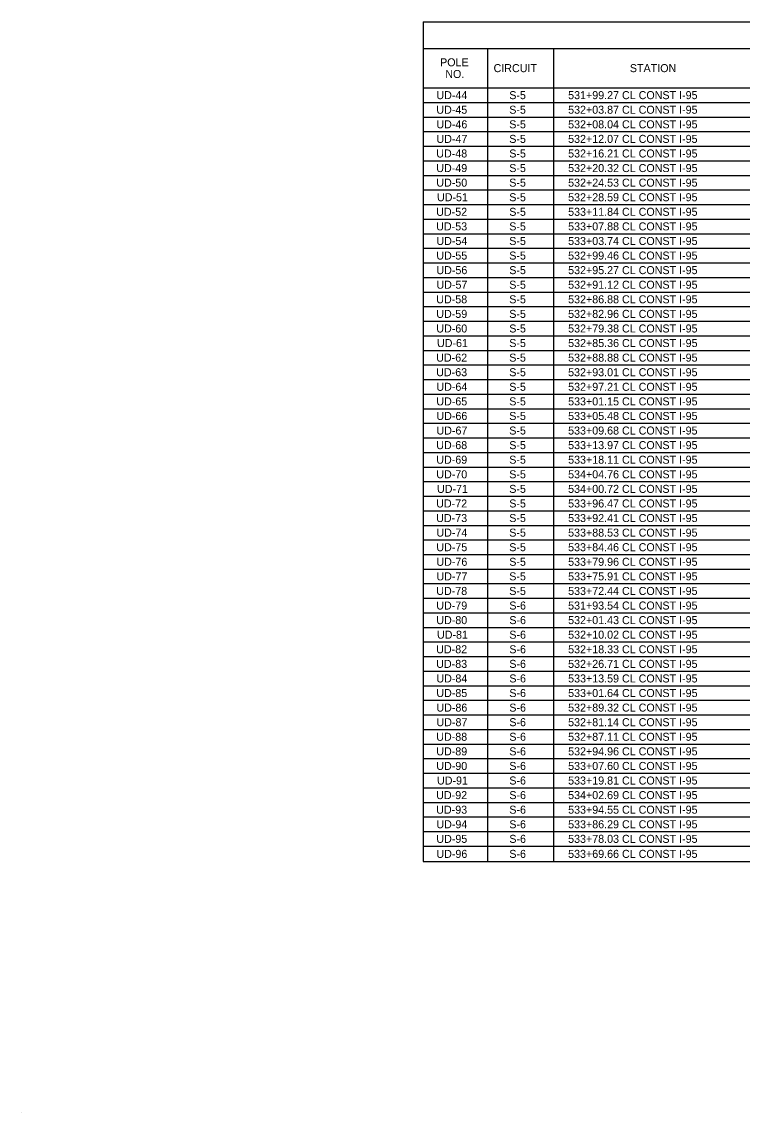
# Model space of a CAD drawing. Extents: x -816.7 to -800.9, y -2209.6 to -2187.8.
# Drawn here: x -816.67 to -810.37, y -2209.64 to -2200.11 of the extents above; entities that cross this region are included whole.
import ezdxf

# ---------------------------------------------------------------- set-up
doc = ezdxf.new("R2010")
doc.units = 0
for name, color, linetype in [('PlotBorder_dp', 7, 'Continuous'), ('SheetBorder_dp', 7, 'Continuous'), ('SheetLines_dp', 7, 'Continuous'), ('TextMinor', 7, 'Continuous'), ('TextShtNo', 7, 'Continuous')]:
    doc.layers.add(name, color=color, linetype=linetype)

msp = doc.modelspace()

# ---------------------------------------------------------------- linework, layer by layer
at = {"layer": 'PlotBorder_dp'}
for p, q in [((-812.5961, -2200.3435), (-812.5961, -2207.4535)), ((-812.5961, -2200.3435), (-812.5961, -2207.4535)), ((-812.0186, -2200.3435), (-812.0186, -2207.4535)), ((-812.0186, -2200.3435), (-812.0186, -2207.4535)), ((-813.1586, -2200.6885), (-802.8536, -2200.6885))]:
    msp.add_line(p, q, dxfattribs=at)
at = {"layer": 'SheetLines_dp'}
for p, q in [((-813.1586, -2200.111), (-802.8536, -2200.111)), ((-813.1586, -2200.111), (-813.1586, -2207.4535)), ((-813.1586, -2200.3435), (-802.8536, -2200.3435)), ((-813.1586, -2200.3435), (-802.8536, -2200.3435)), ((-813.1586, -2207.4535), (-802.8536, -2207.4535))]:
    msp.add_line(p, q, dxfattribs=at)
at = {"layer": 'TextMinor'}
for p, q in [((-813.1586, -2200.6885), (-802.8536, -2200.6885)), ((-813.1586, -2200.816), (-802.8536, -2200.816)), ((-813.1586, -2200.816), (-802.8536, -2200.816)), ((-813.1586, -2200.9435), (-802.8536, -2200.9435)), ((-813.1586, -2200.9435), (-802.8536, -2200.9435)), ((-813.1586, -2201.071), (-802.8536, -2201.071)), ((-813.1586, -2201.071), (-802.8536, -2201.071)), ((-813.1586, -2201.1985), (-802.8536, -2201.1985)), ((-813.1586, -2201.1985), (-802.8536, -2201.1985)), ((-813.1586, -2201.326), (-802.8536, -2201.326)), ((-813.1586, -2201.326), (-802.8536, -2201.326)), ((-813.1586, -2201.4535), (-812.0186, -2201.4535)), ((-813.1586, -2201.4535), (-802.8536, -2201.4535)), ((-813.1586, -2201.581), (-802.8536, -2201.581)), ((-813.1586, -2201.581), (-802.8536, -2201.581)), ((-813.1586, -2201.7085), (-802.8536, -2201.7085)), ((-813.1586, -2201.7085), (-802.8536, -2201.7085)), ((-813.1586, -2201.836), (-802.8536, -2201.836)), ((-813.1586, -2201.836), (-802.8536, -2201.836)), ((-813.1586, -2201.9635), (-802.8536, -2201.9635)), ((-813.1586, -2201.9635), (-802.8536, -2201.9635)), ((-813.1586, -2202.091), (-802.8536, -2202.091)), ((-813.1586, -2202.091), (-802.8536, -2202.091)), ((-813.1586, -2202.2185), (-802.8536, -2202.2185)), ((-813.1586, -2202.2185), (-802.8536, -2202.2185)), ((-813.1586, -2202.346), (-802.8536, -2202.346)), ((-813.1586, -2202.346), (-802.8536, -2202.346)), ((-813.1586, -2202.4735), (-802.8536, -2202.4735)), ((-813.1586, -2202.4735), (-802.8536, -2202.4735)), ((-813.1586, -2202.601), (-802.8536, -2202.601)), ((-813.1586, -2202.601), (-802.8536, -2202.601)), ((-813.1586, -2202.7285), (-802.8536, -2202.7285)), ((-813.1586, -2202.7285), (-802.8536, -2202.7285)), ((-813.1586, -2202.856), (-802.8536, -2202.856)), ((-813.1586, -2202.856), (-802.8536, -2202.856)), ((-813.1586, -2202.9835), (-802.8536, -2202.9835)), ((-813.1586, -2202.9835), (-802.8536, -2202.9835)), ((-813.1586, -2203.111), (-802.8536, -2203.111)), ((-813.1586, -2203.111), (-802.8536, -2203.111)), ((-813.1586, -2203.2385), (-802.8536, -2203.2385)), ((-813.1586, -2203.2385), (-802.8536, -2203.2385)), ((-813.1586, -2203.366), (-802.8536, -2203.366)), ((-813.1586, -2203.366), (-802.8536, -2203.366)), ((-813.1586, -2203.4935), (-802.8536, -2203.4935)), ((-813.1586, -2203.4935), (-802.8536, -2203.4935)), ((-813.1586, -2203.621), (-802.8536, -2203.621)), ((-813.1586, -2203.621), (-802.8536, -2203.621)), ((-813.1586, -2203.7485), (-802.8536, -2203.7485)), ((-813.1586, -2203.7485), (-802.8536, -2203.7485)), ((-813.1586, -2203.876), (-802.8536, -2203.876)), ((-813.1586, -2203.876), (-802.8536, -2203.876)), ((-813.1586, -2204.0035), (-802.8536, -2204.0035)), ((-813.1586, -2204.0035), (-802.8536, -2204.0035)), ((-813.1586, -2204.131), (-802.8536, -2204.131)), ((-813.1586, -2204.131), (-802.8536, -2204.131)), ((-813.1586, -2204.2585), (-802.8536, -2204.2585)), ((-813.1586, -2204.2585), (-802.8536, -2204.2585)), ((-813.1586, -2204.386), (-802.8536, -2204.386)), ((-813.1586, -2204.386), (-802.8536, -2204.386)), ((-813.1586, -2204.5135), (-802.8536, -2204.5135)), ((-813.1586, -2204.5135), (-802.8536, -2204.5135)), ((-813.1586, -2204.641), (-802.8536, -2204.641)), ((-813.1586, -2204.641), (-802.8536, -2204.641)), ((-813.1586, -2204.7685), (-802.8536, -2204.7685)), ((-813.1586, -2204.7685), (-802.8536, -2204.7685)), ((-813.1586, -2204.896), (-802.8536, -2204.896)), ((-813.1586, -2204.896), (-802.8536, -2204.896)), ((-813.1586, -2205.0235), (-802.8536, -2205.0235)), ((-813.1586, -2205.0235), (-802.8536, -2205.0235)), ((-813.1586, -2205.151), (-802.8536, -2205.151)), ((-812.5961, -2205.151), (-812.0186, -2205.151)), ((-813.1586, -2205.2785), (-802.8536, -2205.2785)), ((-813.1586, -2205.2785), (-802.8536, -2205.2785)), ((-813.1586, -2205.406), (-802.8536, -2205.406)), ((-813.1586, -2205.406), (-802.8536, -2205.406)), ((-813.1586, -2205.5335), (-802.8536, -2205.5335)), ((-813.1586, -2205.5335), (-802.8536, -2205.5335)), ((-813.1586, -2205.661), (-802.8536, -2205.661)), ((-813.1586, -2205.661), (-802.8536, -2205.661)), ((-813.1586, -2205.7885), (-802.8536, -2205.7885)), ((-813.1586, -2205.7885), (-802.8536, -2205.7885)), ((-813.1586, -2205.916), (-812.0186, -2205.916)), ((-813.1586, -2205.916), (-802.8536, -2205.916)), ((-813.1586, -2206.0435), (-802.8536, -2206.0435)), ((-813.1586, -2206.0435), (-802.8536, -2206.0435)), ((-813.1586, -2206.171), (-802.8536, -2206.171)), ((-813.1586, -2206.171), (-802.8536, -2206.171)), ((-813.1586, -2206.2985), (-802.8536, -2206.2985)), ((-813.1586, -2206.2985), (-802.8536, -2206.2985)), ((-813.1586, -2206.426), (-802.8536, -2206.426)), ((-813.1586, -2206.426), (-802.8536, -2206.426)), ((-813.1586, -2206.5535), (-802.8536, -2206.5535)), ((-813.1586, -2206.5535), (-802.8536, -2206.5535)), ((-813.1586, -2206.681), (-802.8536, -2206.681)), ((-813.1586, -2206.681), (-802.8536, -2206.681)), ((-813.1586, -2206.8085), (-802.8536, -2206.8085)), ((-813.1586, -2206.8085), (-802.8536, -2206.8085)), ((-813.1586, -2206.936), (-802.8536, -2206.936)), ((-813.1586, -2206.936), (-802.8536, -2206.936)), ((-813.1586, -2207.0635), (-802.8536, -2207.0635)), ((-813.1586, -2207.0635), (-802.8536, -2207.0635)), ((-813.1586, -2207.191), (-802.8536, -2207.191)), ((-813.1586, -2207.191), (-802.8536, -2207.191)), ((-813.1586, -2207.3185), (-802.8536, -2207.3185)), ((-813.1586, -2207.3185), (-802.8536, -2207.3185))]:
    msp.add_line(p, q, dxfattribs=at)
at = {"layer": 'TextShtNo'}
msp.add_line((-816.6686, -2209.6446), (-816.6686, -2209.6446), dxfattribs=at)

# ---------------------------------------------------------------- texts
at = {"layer": 'SheetBorder_dp'}
for s, p in [('POLE', (-813.0106, -2200.5)), ('NO.', (-812.965, -2200.602)), ('CIRCUIT', (-812.5427, -2200.551)), ('STATION', (-811.3507, -2200.551)), ('UD-44', (-813.0429, -2200.7872)), ('S-5', (-812.4056, -2200.7872)), ('531+99.27 CL CONST I-95', (-811.8907, -2200.7872)), ('S-5', (-812.4056, -2200.9147)), ('532+03.87 CL CONST I-95', (-811.8907, -2200.9147)), ('UD-45', (-813.0434, -2200.9147)), ('UD-46', (-813.0429, -2201.0422)), ('S-5', (-812.4056, -2201.0422)), ('532+08.04 CL CONST I-95', (-811.8907, -2201.0422)), ('UD-47', (-813.0423, -2201.1697)), ('S-5', (-812.4056, -2201.1697)), ('532+12.07 CL CONST I-95', (-811.8907, -2201.1697)), ('UD-48', (-813.044, -2201.2972)), ('S-5', (-812.4056, -2201.2972)), ('532+16.21 CL CONST I-95', (-811.8907, -2201.2972)), ('UD-49', (-813.0439, -2201.4247)), ('S-5', (-812.4056, -2201.4247)), ('532+20.32 CL CONST I-95', (-811.8907, -2201.4247)), ('UD-50', (-813.0437, -2201.5522)), ('S-5', (-812.4056, -2201.5522)), ('532+24.53 CL CONST I-95', (-811.8907, -2201.5522)), ('UD-51', (-813.0375, -2201.6797)), ('S-5', (-812.4056, -2201.6797)), ('532+28.59 CL CONST I-95', (-811.8907, -2201.6797)), ('UD-52', (-813.0443, -2201.8072)), ('S-5', (-812.4056, -2201.8072)), ('533+11.84 CL CONST I-95', (-811.8907, -2201.8072)), ('UD-53', (-813.0443, -2201.9347)), ('S-5', (-812.4056, -2201.9347)), ('533+07.88 CL CONST I-95', (-811.8907, -2201.9347)), ('UD-54', (-813.0429, -2202.0622)), ('S-5', (-812.4056, -2202.0622)), ('533+03.74 CL CONST I-95', (-811.8907, -2202.0622)), ('UD-55', (-813.0434, -2202.1897)), ('S-5', (-812.4056, -2202.1897)), ('532+99.46 CL CONST I-95', (-811.8907, -2202.1897)), ('UD-56', (-813.0429, -2202.3172)), ('S-5', (-812.4056, -2202.3172)), ('532+95.27 CL CONST I-95', (-811.8907, -2202.3172)), ('UD-57', (-813.0423, -2202.4447)), ('S-5', (-812.4056, -2202.4447)), ('532+91.12 CL CONST I-95', (-811.8907, -2202.4447)), ('UD-58', (-813.044, -2202.5722)), ('S-5', (-812.4056, -2202.5722)), ('532+86.88 CL CONST I-95', (-811.8907, -2202.5722)), ('UD-59', (-813.0439, -2202.6997)), ('S-5', (-812.4056, -2202.6997)), ('532+82.96 CL CONST I-95', (-811.8907, -2202.6997)), ('UD-60', (-813.0437, -2202.8272)), ('S-5', (-812.4056, -2202.8272)), ('532+79.38 CL CONST I-95', (-811.8907, -2202.8272)), ('UD-61', (-813.0375, -2202.9547)), ('S-5', (-812.4056, -2202.9547)), ('532+85.36 CL CONST I-95', (-811.8907, -2202.9547)), ('UD-62', (-813.0443, -2203.0822)), ('S-5', (-812.4056, -2203.0822)), ('532+88.88 CL CONST I-95', (-811.8907, -2203.0822)), ('UD-63', (-813.0443, -2203.2097)), ('S-5', (-812.4056, -2203.2097)), ('532+93.01 CL CONST I-95', (-811.8907, -2203.2097)), ('UD-64', (-813.0429, -2203.3372)), ('S-5', (-812.4056, -2203.3372)), ('532+97.21 CL CONST I-95', (-811.8907, -2203.3372)), ('UD-65', (-813.0434, -2203.4647)), ('S-5', (-812.4056, -2203.4647)), ('533+01.15 CL CONST I-95', (-811.8907, -2203.4647)), ('UD-66', (-813.0429, -2203.5922)), ('S-5', (-812.4056, -2203.5922)), ('533+05.48 CL CONST I-95', (-811.8907, -2203.5922)), ('UD-67', (-813.0423, -2203.7197)), ('S-5', (-812.4056, -2203.7197)), ('533+09.68 CL CONST I-95', (-811.8907, -2203.7197)), ('UD-68', (-813.044, -2203.8472)), ('S-5', (-812.4056, -2203.8472)), ('533+13.97 CL CONST I-95', (-811.8907, -2203.8472)), ('UD-69', (-813.0439, -2203.9747)), ('S-5', (-812.4056, -2203.9747)), ('533+18.11 CL CONST I-95', (-811.8907, -2203.9747)), ('UD-70', (-813.0437, -2204.1022)), ('S-5', (-812.4056, -2204.1022)), ('534+04.76 CL CONST I-95', (-811.8907, -2204.1022)), ('UD-71', (-813.0375, -2204.2297)), ('S-5', (-812.4056, -2204.2297)), ('534+00.72 CL CONST I-95', (-811.8907, -2204.2297)), ('UD-72', (-813.0443, -2204.3572)), ('S-5', (-812.4056, -2204.3572)), ('533+96.47 CL CONST I-95', (-811.8907, -2204.3572)), ('UD-73', (-813.0443, -2204.4847)), ('S-5', (-812.4056, -2204.4847)), ('533+92.41 CL CONST I-95', (-811.8907, -2204.4847)), ('UD-74', (-813.0429, -2204.6122)), ('S-5', (-812.4056, -2204.6122)), ('533+88.53 CL CONST I-95', (-811.8907, -2204.6122)), ('UD-75', (-813.0434, -2204.7397)), ('S-5', (-812.4056, -2204.7397)), ('533+84.46 CL CONST I-95', (-811.8907, -2204.7397)), ('UD-76', (-813.0429, -2204.8672)), ('S-5', (-812.4056, -2204.8672)), ('533+79.96 CL CONST I-95', (-811.8907, -2204.8672)), ('UD-77', (-813.0423, -2204.9947)), ('S-5', (-812.4056, -2204.9947)), ('533+75.91 CL CONST I-95', (-811.8907, -2204.9947)), ('UD-78', (-813.044, -2205.1222)), ('S-5', (-812.4056, -2205.1222)), ('533+72.44 CL CONST I-95', (-811.8907, -2205.1222)), ('UD-79', (-813.0439, -2205.2497)), ('S-6', (-812.4051, -2205.2497)), ('531+93.54 CL CONST I-95', (-811.8907, -2205.2497)), ('UD-80', (-813.0437, -2205.3772)), ('S-6', (-812.4051, -2205.3772)), ('532+01.43 CL CONST I-95', (-811.8907, -2205.3772)), ('UD-81', (-813.0375, -2205.5047)), ('S-6', (-812.4051, -2205.5047)), ('532+10.02 CL CONST I-95', (-811.8907, -2205.5047)), ('UD-82', (-813.0443, -2205.6322)), ('S-6', (-812.4051, -2205.6322)), ('532+18.33 CL CONST I-95', (-811.8907, -2205.6322)), ('UD-83', (-813.0443, -2205.7597)), ('S-6', (-812.4051, -2205.7597)), ('532+26.71 CL CONST I-95', (-811.8907, -2205.7597)), ('UD-84', (-813.0429, -2205.8872)), ('S-6', (-812.4051, -2205.8872)), ('533+13.59 CL CONST I-95', (-811.8907, -2205.8872)), ('UD-85', (-813.0434, -2206.0147)), ('S-6', (-812.4051, -2206.0147)), ('533+01.64 CL CONST I-95', (-811.8907, -2206.0147)), ('UD-86', (-813.0429, -2206.1422)), ('S-6', (-812.4051, -2206.1422)), ('532+89.32 CL CONST I-95', (-811.8907, -2206.1422)), ('UD-87', (-813.0423, -2206.2697)), ('S-6', (-812.4051, -2206.2697)), ('532+81.14 CL CONST I-95', (-811.8907, -2206.2697)), ('UD-88', (-813.044, -2206.3972)), ('S-6', (-812.4051, -2206.3972)), ('532+87.11 CL CONST I-95', (-811.8907, -2206.3972)), ('UD-89', (-813.0439, -2206.5247)), ('S-6', (-812.4051, -2206.5247)), ('532+94.96 CL CONST I-95', (-811.8907, -2206.5247)), ('UD-90', (-813.0437, -2206.6522)), ('S-6', (-812.4051, -2206.6522)), ('533+07.60 CL CONST I-95', (-811.8907, -2206.6522)), ('UD-91', (-813.0375, -2206.7797)), ('S-6', (-812.4051, -2206.7797)), ('533+19.81 CL CONST I-95', (-811.8907, -2206.7797)), ('UD-92', (-813.0443, -2206.9072)), ('S-6', (-812.4051, -2206.9072)), ('534+02.69 CL CONST I-95', (-811.8907, -2206.9072)), ('UD-93', (-813.0443, -2207.0347)), ('S-6', (-812.4051, -2207.0347)), ('533+94.55 CL CONST I-95', (-811.8907, -2207.0347)), ('UD-94', (-813.0429, -2207.1622)), ('S-6', (-812.4051, -2207.1622)), ('533+86.29 CL CONST I-95', (-811.8907, -2207.1622)), ('UD-95', (-813.0434, -2207.2897)), ('S-6', (-812.4051, -2207.2897)), ('533+78.03 CL CONST I-95', (-811.8907, -2207.2897)), ('UD-96', (-813.0429, -2207.421)), ('S-6', (-812.4051, -2207.421)), ('533+69.66 CL CONST I-95', (-811.8907, -2207.421))]:
    msp.add_text(s, height=0.07, dxfattribs=at).set_placement(p)

doc.saveas('drawing.dxf')
